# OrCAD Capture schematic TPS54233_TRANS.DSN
size Custom; title: TPS54233 :2A, 28V INPUT, STEP DOWN SWIFT; rev: 1.1; note: Datasheet:SLUS859C       EVM:SLVU264A
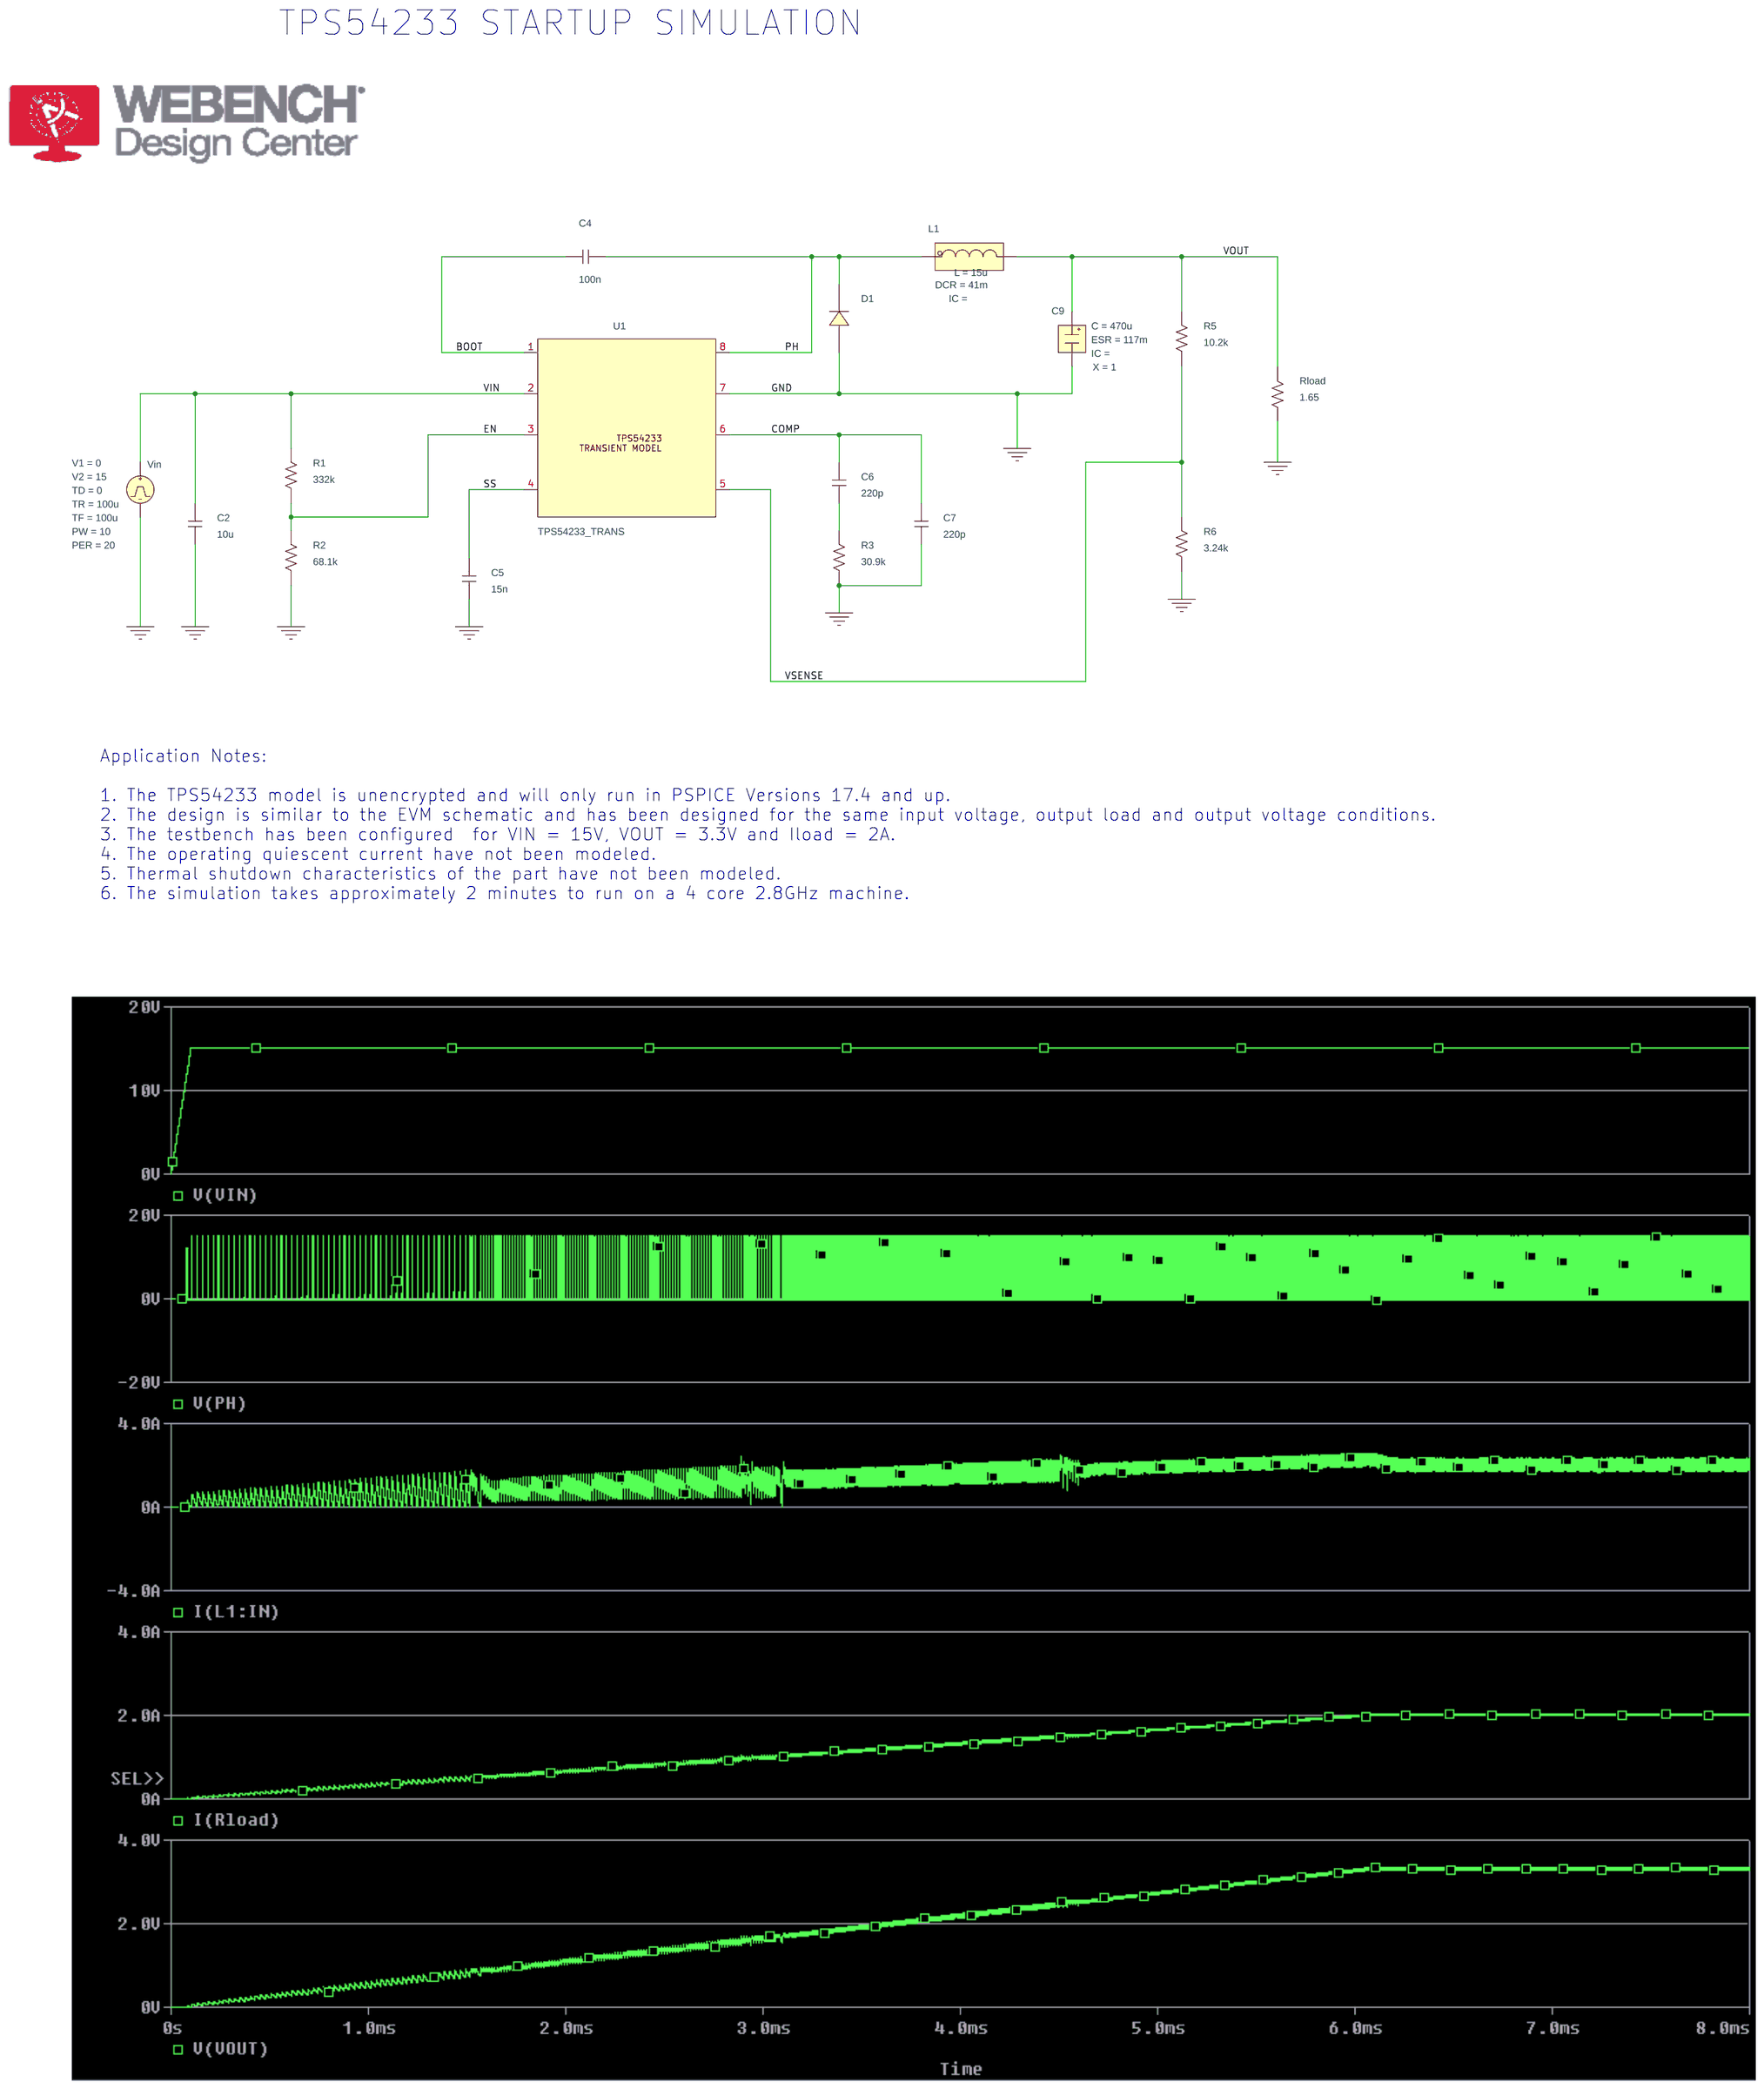
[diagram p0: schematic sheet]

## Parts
C2  10u  [RAD/CK05]
C4  100n  [RAD/CK05]
C5  15n  [RAD/CK05]
C6  220p  [RAD/CK05]
C7  220p  [RAD/CK05]
C9  CESR
D1  B230A
L1  LDCR
R1  332k  [AX/RC05]
R2  68.1k  [AX/RC05]
R3  30.9k  [AX/RC05]
R5  10.2k  [AX/RC05]
R6  3.24k  [AX/RC05]
Rload  1.65  [AX/RC05]
U1  TPS54233_TRANS
Vin  VPULSE

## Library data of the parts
C2 C4-C7 = C
C9 = CESR: C: 470u; ESR: 117m; X: 1
D1 = D_DIDEAL_0
L1 = LDCR: DCR: 41m; L: 15u
R1-R3 R5 R6 Rload = R
U1 = TPS54233_TRANS
Vin = VPULSE: PER: 20; PW: 10; TD: 0; TF: 100u; TR: 100u; V1: 0; V2: 15

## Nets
VIN: C2.2 R1.2 U1.2(VIN) Vin.1(+)
0: C2.1 C5.1 C7.1 C9.2(OUT) D1.2(A) R2.1 R3.1 R6.1 Rload.2 U1.7(GND) Vin.2(-)
BOOT: C4.2 U1.1(BOOT)
COMP: C6.2 C7.2 U1.6(COMP)
EN: R1.1 R2.2 U1.3(EN)
PH: C4.1 D1.1(C) L1.1(IN) U1.8(PH)
SS: C5.2 U1.4(SS)
VOUT: C9.1(IN) L1.2(OUT) R5.2 Rload.1
VSENSE: R5.1 R6.2 U1.5(VSENSE)
N00603: C6.1 R3.2

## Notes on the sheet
- TPS54233 STARTUP SIMULATION
- Application Notes:
  1. The TPS54233 model is unencrypted and will only run in PSPICE Versions 17.4 and up.
  2. The design is similar to the EVM schematic and has been designed for the same input voltage, output load and output voltage conditions.
  3. The testbench has been configured  for VIN = 15V, VOUT = 3.3V and Iload = 2A.
  4. The operating quiescent current have not been modeled.
  5. Thermal shutdown characteristics of the part have not been modeled.
  6. The simulation takes approximately 2 minutes to run on a 4 core 2.8GHz machine.
